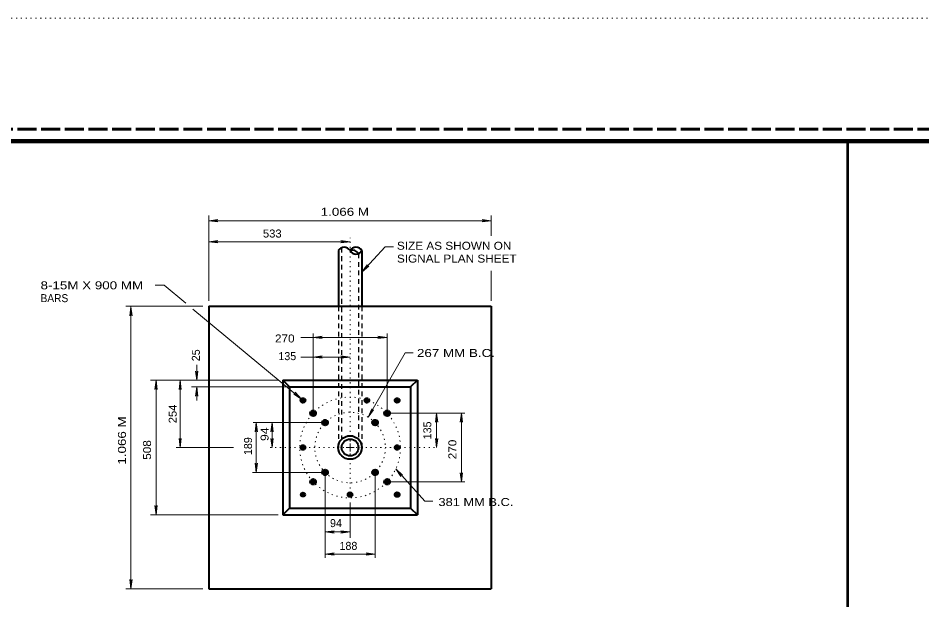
# Model space of a CAD drawing. Extents: x 312583 to 312854, y 144419 to 144597.
# Drawn here: x 312631.8 to 312717.6, y 144541.5 to 144596.8 of the extents above; entities that cross this region are included whole.
import ezdxf

# ---------------------------------------------------------------- set-up
doc = ezdxf.new("R2010")
doc.units = 0
doc.header["$LTSCALE"] = 0.3
for name, pattern in [('DOTTED', [1.5, 0.3, -1.2]), ('LONG_DASHED', [7.5, 6, -1.5]), ('SHORT_DASHED', [2.7, 1.5, -1.2])]:
    doc.linetypes.add(name, pattern=pattern)
for name, color, linetype, lineweight in [('1', 7, 'Continuous', 40), ('2', 7, 'Continuous', 13), ('62', 7, 'DOTTED', 13), ('63', 7, 'LONG_DASHED', 60)]:
    doc.layers.add(name, color=color, linetype=linetype, lineweight=lineweight)

msp = doc.modelspace()

# ---------------------------------------------------------------- linework, layer by layer
at = {"layer": '1', "lineweight": 53}
msp.add_line((312710.5662, 144423.0846), (312710.5662, 144585.0846), dxfattribs=at)
at = {"layer": '1'}
for p, q in [((312662.1716, 144574.688), (312662.1716, 144569.398)), ((312664.4026, 144574.688), (312664.4026, 144569.398)), ((312649.8666, 144569.398), (312676.7, 144569.398)), ((312649.8666, 144569.398), (312649.8666, 144542.5647)), ((312676.7, 144569.398), (312676.7, 144542.5647)), ((312656.897, 144562.3677), (312669.6773, 144562.3677)), ((312656.897, 144562.3677), (312656.897, 144549.595)), ((312656.897, 144562.3677), (312657.5333, 144561.7313)), ((312669.6773, 144562.3677), (312669.0333, 144561.7313)), ((312669.6773, 144562.3677), (312669.6773, 144549.595)), ((312657.5333, 144561.7313), (312669.0333, 144561.7313)), ((312657.5333, 144561.7313), (312657.5333, 144550.2313)), ((312669.0333, 144561.7313), (312669.0333, 144550.2313)), ((312657.5333, 144550.2313), (312656.897, 144549.595)), ((312657.5333, 144550.2313), (312669.0333, 144550.2313)), ((312669.0333, 144550.2313), (312669.6773, 144549.595)), ((312656.897, 144549.595), (312669.6773, 144549.595)), ((312649.8666, 144542.5647), (312676.7, 144542.5647))]:
    msp.add_line(p, q, dxfattribs=at)
at = {"layer": '1', "linetype": 'SHORT_DASHED', "lineweight": 25}
for p, q in [((312662.486, 144574.9563), (312662.486, 144556.7633)), ((312664.0883, 144574.412), (312664.0883, 144556.7633)), ((312662.1716, 144569.398), (312662.1716, 144555.9813)), ((312664.4026, 144569.398), (312664.4026, 144555.9813))]:
    msp.add_line(p, q, dxfattribs=at)
at = {"layer": '1', "lineweight": 158}
msp.add_lwpolyline([(312616.5, 144423.1446), (312616.5, 144585.0846), (312849, 144585.0846)], dxfattribs=at)
at = {"layer": '1', "linetype": 'DOTTED', "lineweight": 13}
for radius in [4.7917, 3.3542]:
    msp.add_circle((312663.2859, 144555.9801), radius, dxfattribs=at)
at = {"layer": '1', "lineweight": 53}
for centre, radius in [((312658.8136, 144560.4523), 0.1917), ((312658.8136, 144560.4523), 0.0958), ((312664.8831, 144560.4523), 0.1917), ((312664.8831, 144560.4523), 0.0958), ((312667.7581, 144560.4523), 0.1917), ((312667.7581, 144560.4523), 0.0958), ((312659.772, 144559.2378), 0.2396), ((312659.772, 144559.2378), 0.1198), ((312666.7997, 144559.2378), 0.2396), ((312666.7997, 144559.2378), 0.1198), ((312660.906, 144558.3439), 0.2396), ((312660.906, 144558.3439), 0.1198), ((312665.6657, 144558.3439), 0.2396), ((312665.6657, 144558.3439), 0.1198), ((312658.8136, 144555.9801), 0.1917), ((312667.7581, 144555.9801), 0.1917), ((312658.8136, 144555.9801), 0.0958), ((312667.7581, 144555.9801), 0.0958), ((312660.906, 144553.6162), 0.2396), ((312660.906, 144553.6162), 0.1198), ((312665.6657, 144553.6162), 0.2396), ((312665.6657, 144553.6162), 0.1198), ((312659.772, 144552.7224), 0.2396), ((312659.772, 144552.7224), 0.1198), ((312666.7997, 144552.7224), 0.2396), ((312666.7997, 144552.7224), 0.1198), ((312663.2859, 144551.5078), 0.1917), ((312663.2859, 144551.5078), 0.0958), ((312667.7581, 144551.5078), 0.1917), ((312667.7581, 144551.5078), 0.0958)]:
    msp.add_circle(centre, radius, dxfattribs=at)
at = {"layer": '1'}
for centre, radius in [((312663.2859, 144555.9801), 1.1181), ((312663.2859, 144555.9801), 0.7986), ((312658.8136, 144551.5078), 0.1917), ((312658.8136, 144551.5078), 0.0958)]:
    msp.add_circle(centre, radius, dxfattribs=at)
for centre, start, end in [((312662.7268, 144574.3548), 30.60313, 149.39687), ((312663.5254, 144574.082), 30.60313, 111.65707), ((312663.8449, 144574.3548), 30.60313, 149.39687), ((312663.8449, 144575.0161), 210.60313, 329.39687)]:
    msp.add_arc(centre, 0.6495, start, end, dxfattribs=at)
at = {"layer": '2'}
for p, q in [((312649.8666, 144569.9117), (312649.8666, 144578.0153)), ((312649.8666, 144577.5247), (312650.733, 144577.632)), ((312650.733, 144577.632), (312650.457, 144577.5247)), ((312675.8336, 144577.632), (312676.1096, 144577.5247)), ((312676.7, 144577.5247), (312675.8336, 144577.632)), ((312676.7, 144576.091), (312676.7, 144578.0153)), ((312676.7, 144577.5247), (312649.8666, 144577.5247)), ((312649.8666, 144577.5247), (312650.733, 144577.4173)), ((312650.733, 144577.4173), (312650.457, 144577.5247)), ((312675.8336, 144577.4173), (312676.1096, 144577.5247)), ((312676.7, 144577.5247), (312675.8336, 144577.4173)), ((312649.8666, 144575.5313), (312650.733, 144575.6387)), ((312663.2833, 144575.5313), (312649.8666, 144575.5313)), ((312649.8666, 144575.5313), (312650.733, 144575.424)), ((312650.733, 144575.6387), (312650.457, 144575.5313)), ((312650.733, 144575.424), (312650.457, 144575.5313)), ((312662.417, 144575.6387), (312662.693, 144575.5313)), ((312663.2833, 144575.5313), (312662.417, 144575.6387)), ((312662.417, 144575.424), (312662.693, 144575.5313)), ((312663.2833, 144575.5313), (312662.417, 144575.424)), ((312664.4026, 144572.6257), (312664.9086, 144573.3387)), ((312664.9086, 144573.3387), (312664.8013, 144573.0627)), ((312664.4026, 144572.6257), (312665.062, 144573.2007)), ((312665.062, 144573.2007), (312664.8013, 144573.0627)), ((312676.7, 144569.9117), (312676.7, 144572.7713)), ((312645.627, 144571.399), (312644.7606, 144571.399)), ((312647.697, 144569.6817), (312645.627, 144571.399)), ((312649.2916, 144569.398), (312641.9853, 144569.398)), ((312642.4683, 144569.3443), (312642.361, 144568.478)), ((312642.4683, 144542.5647), (312642.4683, 144569.3443)), ((312642.4683, 144569.3443), (312642.5756, 144568.478)), ((312658.6756, 144560.589), (312648.364, 144569.1297)), ((312642.361, 144568.478), (312642.4683, 144568.754)), ((312642.5756, 144568.478), (312642.4683, 144568.754)), ((312666.8023, 144566.4387), (312658.6066, 144566.4387)), ((312659.772, 144559.2397), (312659.772, 144566.822)), ((312659.772, 144566.4387), (312660.6383, 144566.546)), ((312659.772, 144566.4387), (312660.6383, 144566.3313)), ((312660.6383, 144566.546), (312660.3623, 144566.4387)), ((312660.6383, 144566.3313), (312660.3623, 144566.4387)), ((312665.936, 144566.546), (312666.212, 144566.4387)), ((312666.8023, 144566.4387), (312665.936, 144566.546)), ((312665.936, 144566.3313), (312666.212, 144566.4387)), ((312666.8023, 144566.4387), (312665.936, 144566.3313)), ((312666.8023, 144559.2397), (312666.8023, 144566.822)), ((312663.2833, 144564.5757), (312658.6066, 144564.5757)), ((312659.772, 144564.5757), (312660.6383, 144564.683)), ((312659.772, 144564.5757), (312660.6383, 144564.4683)), ((312660.6383, 144564.683), (312660.3623, 144564.5757)), ((312660.6383, 144564.4683), (312660.3623, 144564.5757)), ((312662.417, 144564.683), (312662.693, 144564.5757)), ((312663.2833, 144564.5757), (312662.417, 144564.683)), ((312662.417, 144564.4683), (312662.693, 144564.5757)), ((312663.2833, 144564.5757), (312662.417, 144564.4683)), ((312648.617, 144563.234), (312648.7243, 144562.958)), ((312648.7243, 144562.3677), (312648.617, 144563.234)), ((312648.7243, 144562.3677), (312648.7243, 144563.8243)), ((312648.8316, 144563.234), (312648.7243, 144562.958)), ((312648.7243, 144562.3677), (312648.8316, 144563.234)), ((312656.4523, 144562.3677), (312644.3236, 144562.3677)), ((312644.8526, 144562.3677), (312644.7453, 144561.5013)), ((312644.8526, 144549.595), (312644.8526, 144562.3677)), ((312644.8526, 144562.3677), (312644.96, 144561.5013)), ((312647.145, 144562.3677), (312647.0376, 144561.5013)), ((312647.145, 144555.9813), (312647.145, 144562.3677)), ((312647.145, 144562.3677), (312647.2523, 144561.5013)), ((312644.7453, 144561.5013), (312644.8526, 144561.7773)), ((312644.96, 144561.5013), (312644.8526, 144561.7773)), ((312647.0376, 144561.5013), (312647.145, 144561.7773)), ((312647.2523, 144561.5013), (312647.145, 144561.7773)), ((312657.5333, 144561.7313), (312648.2106, 144561.7313)), ((312648.7243, 144561.7313), (312648.617, 144560.865)), ((312648.7243, 144560.4587), (312648.7243, 144561.7313)), ((312648.7243, 144561.7313), (312648.8316, 144560.865)), ((312648.617, 144560.865), (312648.7243, 144561.141)), ((312648.8316, 144560.865), (312648.7243, 144561.141)), ((312657.9396, 144561.0567), (312658.2233, 144560.9647)), ((312658.6756, 144560.589), (312657.9396, 144561.0567)), ((312658.0776, 144561.2253), (312658.2233, 144560.9647)), ((312658.6756, 144560.589), (312658.0776, 144561.2253)), ((312664.993, 144558.864), (312665.338, 144559.669)), ((312665.338, 144559.669), (312665.292, 144559.3777)), ((312664.993, 144558.864), (312665.522, 144559.5617)), ((312665.522, 144559.5617), (312665.292, 144559.3777)), ((312666.8023, 144559.2397), (312674.1853, 144559.2397)), ((312671.5096, 144559.2397), (312671.4023, 144558.3733)), ((312671.5096, 144555.9813), (312671.5096, 144559.2397)), ((312671.5096, 144559.2397), (312671.617, 144558.3733)), ((312673.8556, 144559.2397), (312673.7483, 144558.3733)), ((312673.8556, 144552.723), (312673.8556, 144559.2397)), ((312673.8556, 144559.2397), (312673.963, 144558.3733)), ((312660.9066, 144558.3427), (312654.0756, 144558.3427)), ((312654.3746, 144558.3427), (312654.2673, 144557.4763)), ((312654.3746, 144553.62), (312654.3746, 144558.3427)), ((312654.3746, 144558.3427), (312654.482, 144557.4763)), ((312655.8773, 144558.3427), (312655.77, 144557.4763)), ((312655.8773, 144555.9813), (312655.8773, 144558.3427)), ((312655.8773, 144558.3427), (312655.9846, 144557.4763)), ((312671.4023, 144558.3733), (312671.5096, 144558.6493)), ((312671.617, 144558.3733), (312671.5096, 144558.6493)), ((312673.7483, 144558.3733), (312673.8556, 144558.6493)), ((312673.963, 144558.3733), (312673.8556, 144558.6493)), ((312654.2673, 144557.4763), (312654.3746, 144557.7523)), ((312654.482, 144557.4763), (312654.3746, 144557.7523)), ((312655.77, 144557.4763), (312655.8773, 144557.7523)), ((312655.9846, 144557.4763), (312655.8773, 144557.7523)), ((312647.0376, 144556.8477), (312647.145, 144556.5717)), ((312647.145, 144555.9813), (312647.0376, 144556.8477)), ((312647.2523, 144556.8477), (312647.145, 144556.5717)), ((312647.145, 144555.9813), (312647.2523, 144556.8477)), ((312655.77, 144556.8477), (312655.8773, 144556.5717)), ((312655.8773, 144555.9813), (312655.77, 144556.8477)), ((312655.9846, 144556.8477), (312655.8773, 144556.5717)), ((312655.8773, 144555.9813), (312655.9846, 144556.8477)), ((312663.2833, 144555.9813), (312663.2833, 144556.3647)), ((312671.4023, 144556.8477), (312671.5096, 144556.5717)), ((312671.5096, 144555.9813), (312671.4023, 144556.8477)), ((312671.617, 144556.8477), (312671.5096, 144556.5717)), ((312671.5096, 144555.9813), (312671.617, 144556.8477)), ((312652.2203, 144555.9813), (312646.7616, 144555.9813)), ((312663.2833, 144555.9813), (312662.9, 144555.9813)), ((312663.2833, 144555.9813), (312663.6666, 144555.9813)), ((312663.2833, 144555.9813), (312663.2833, 144555.598)), ((312654.2673, 144554.4863), (312654.3746, 144554.2103)), ((312654.3746, 144553.62), (312654.2673, 144554.4863)), ((312654.482, 144554.4863), (312654.3746, 144554.2103)), ((312654.3746, 144553.62), (312654.482, 144554.4863)), ((312660.9066, 144553.62), (312654.0143, 144553.62)), ((312660.9066, 144553.62), (312660.9066, 144545.5087)), ((312665.6676, 144553.62), (312665.6676, 144545.5087)), ((312667.6226, 144553.942), (312668.121, 144553.2213)), ((312667.6226, 144553.942), (312668.282, 144553.367)), ((312673.7483, 144553.5893), (312673.8556, 144553.3133)), ((312673.8556, 144552.723), (312673.7483, 144553.5893)), ((312673.963, 144553.5893), (312673.8556, 144553.3133)), ((312673.8556, 144552.723), (312673.963, 144553.5893)), ((312666.8023, 144552.723), (312674.1853, 144552.723)), ((312668.121, 144553.2213), (312668.0136, 144553.4973)), ((312668.282, 144553.367), (312668.0136, 144553.4973)), ((312644.7453, 144550.4613), (312644.8526, 144550.1853)), ((312644.8526, 144549.595), (312644.7453, 144550.4613)), ((312644.96, 144550.4613), (312644.8526, 144550.1853)), ((312644.8526, 144549.595), (312644.96, 144550.4613)), ((312663.2859, 144550.7524), (312663.2859, 144547.4013)), ((312656.4523, 144549.595), (312644.3236, 144549.595)), ((312660.9066, 144547.9543), (312661.773, 144548.0617)), ((312660.9066, 144547.9543), (312661.773, 144547.847)), ((312663.2833, 144547.9543), (312660.9066, 144547.9543)), ((312661.773, 144548.0617), (312661.497, 144547.9543)), ((312661.773, 144547.847), (312661.497, 144547.9543)), ((312662.417, 144548.0617), (312662.693, 144547.9543)), ((312663.2833, 144547.9543), (312662.417, 144548.0617)), ((312662.417, 144547.847), (312662.693, 144547.9543)), ((312663.2833, 144547.9543), (312662.417, 144547.847)), ((312660.9066, 144545.8537), (312661.773, 144545.961)), ((312665.6676, 144545.8537), (312660.9066, 144545.8537)), ((312660.9066, 144545.8537), (312661.773, 144545.7463)), ((312661.773, 144545.961), (312661.497, 144545.8537)), ((312661.773, 144545.7463), (312661.497, 144545.8537)), ((312664.8013, 144545.961), (312665.0773, 144545.8537)), ((312665.6676, 144545.8537), (312664.8013, 144545.961)), ((312664.8013, 144545.7463), (312665.0773, 144545.8537)), ((312665.6676, 144545.8537), (312664.8013, 144545.7463)), ((312642.361, 144543.431), (312642.4683, 144543.155)), ((312642.4683, 144542.5647), (312642.361, 144543.431)), ((312642.5756, 144543.431), (312642.4683, 144543.155)), ((312642.4683, 144542.5647), (312642.5756, 144543.431)), ((312649.2916, 144542.5647), (312641.9853, 144542.5647))]:
    msp.add_line(p, q, dxfattribs=at)
at = {"layer": '2', "linetype": 'DOTTED'}
for p, q in [((312663.2833, 144556.5563), (312663.2833, 144575.8917)), ((312662.7083, 144555.9813), (312655.517, 144555.9813)), ((312663.2833, 144555.4063), (312663.2833, 144551.4218)), ((312663.8583, 144555.9813), (312671.5403, 144555.9813))]:
    msp.add_line(p, q, dxfattribs=at)
at = {"layer": '2'}
for points in [[(312664.4026, 144572.6257), (312666.6106, 144575.0637), (312667.4156, 144575.0637)], [(312664.993, 144558.864), (312668.5273, 144564.9897), (312669.2786, 144564.9897)], [(312667.6226, 144553.942), (312670.3903, 144550.8677), (312671.1493, 144550.8677)]]:
    msp.add_lwpolyline(points, dxfattribs=at)
at = {"layer": '62'}
msp.add_line((312601.2, 144596.7846), (312853.5, 144596.7846), dxfattribs=at)
at = {"layer": '63'}
msp.add_line((312851.75, 144586.2246), (312583.526, 144586.2246), dxfattribs=at)

# ---------------------------------------------------------------- texts
at = {"layer": '2'}
for s, width, p in [('1.066 M', 1.25, (312660.4959, 144577.9965)), ('533', 1.05, (312655.0058, 144575.9329)), ('SIZE AS SHOWN ON', 1.1, (312667.7376, 144574.7713)), ('SIGNAL PLAN SHEET', 1.1, (312667.7376, 144573.5513)), ('8-15M X 900 MM', 1.25, (312633.8862, 144571.0113)), ('BARS', 0.95, (312633.8862, 144569.7913)), ('270', 1.1, (312656.1516, 144565.9594)), ('267 MM B.C.', 1.25, (312669.639, 144564.5793)), ('381 MM B.C.', 1.2, (312671.6815, 144550.419))]:
    msp.add_text(s, height=0.76, dxfattribs=dict(at, width=width)).set_placement(p)
for s, p in [('25', (312649.0179, 144564.1782)), ('135', (312671.0027, 144556.7562)), ('189', (312653.9739, 144555.2601))]:
    msp.add_text(s, height=0.76, rotation=90, dxfattribs=at).set_placement(p)
for s, p in [('135', (312656.4759, 144564.2827)), ('94', (312661.3814, 144548.4166)), ('188', (312662.2821, 144546.2553))]:
    msp.add_text(s, height=0.76, dxfattribs=at).set_placement(p)
for s, width, p in [('254', 1.05, (312646.8145, 144558.2823)), ('1.066 M', 1.25, (312641.9976, 144554.3528)), ('94 ', 1.15, (312655.5463, 144556.5958)), ('508', 1.1, (312644.3818, 144554.8124)), ('270', 1.1, (312673.3848, 144554.8618))]:
    msp.add_text(s, height=0.76, rotation=90, dxfattribs=dict(at, width=width)).set_placement(p)

doc.saveas('drawing.dxf')
